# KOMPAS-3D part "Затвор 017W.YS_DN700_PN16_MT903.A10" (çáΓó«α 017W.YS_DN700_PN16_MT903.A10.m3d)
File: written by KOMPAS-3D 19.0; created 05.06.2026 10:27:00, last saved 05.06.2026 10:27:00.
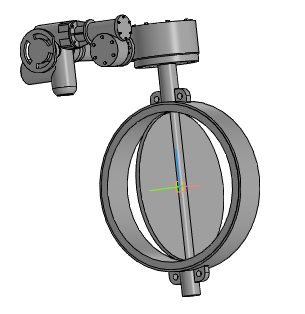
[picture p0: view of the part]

Document properties: Автор: Энергия; Полное имя файла: ..\..\..\3d для проектировщиков\x.x Тип 017W.Y(S) Затвор дисковый поворотный межфланцевый\Затвор 017W.Y(S)_DN32-DN1200_QT.A_MT903.A\Затвор 017W.YS_DN700_PN16_MT903.A10.a3d

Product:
- Part/product: Затвор 017W.YS_DN700_PN16_MT903.A10
    Масса: 461.765

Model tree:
1. Операция без истории:1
